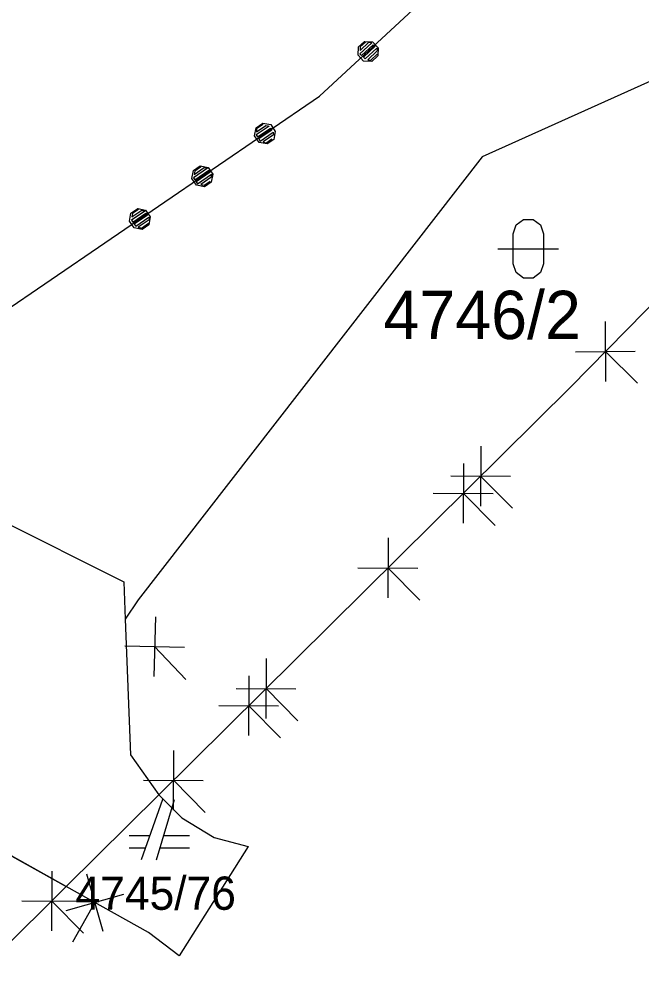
# Model space of a CAD drawing. Extents: x -266179 to -264727, y -1243225 to -1241702.
# Drawn here: x -265749.17 to -265728.53, y -1241952.44 to -1241920.85 of the extents above; entities that cross this region are included whole.
import ezdxf

# ---------------------------------------------------------------- set-up
doc = ezdxf.new("R2010")
doc.units = 0
for name, color, linetype in [('Vrstva 1', 7, 'Continuous'), ('Vrstva 19', 7, 'Continuous'), ('Vrstva 21', 7, 'Continuous')]:
    doc.layers.add(name, color=color, linetype=linetype)

msp = doc.modelspace()

# ---------------------------------------------------------------- linework, layer by layer
at = {"layer": 'Vrstva 1'}
for p, q in [((-265739.22, -1241923.41), (-265729.78, -1241914.67)), ((-265715.41, -1241917.13), (-265733.82, -1241925.42)), ((-265719.23, -1241921.16), (-265730.9, -1241933.04)), ((-265755.57, -1241934.56), (-265739.22, -1241923.41)), ((-265733.82, -1241925.42), (-265745.23, -1241940.09)), ((-265730.9, -1241933.04), (-265744.54, -1241946.54)), ((-265755.57, -1241934.56), (-265745.7, -1241939.49)), ((-265745.7, -1241939.49), (-265745.65, -1241940.73)), ((-265745.23, -1241940.09), (-265745.65, -1241940.73)), ((-265745.65, -1241940.73), (-265745.48, -1241945.22)), ((-265745.48, -1241945.22), (-265744.54, -1241946.54)), ((-265744.54, -1241946.54), (-265747.61, -1241949.58)), ((-265744.42, -1241946.7), (-265745.12, -1241948.7)), ((-265744.62, -1241948.7), (-265744.02, -1241946.7)), ((-265744.54, -1241946.54), (-265743.78, -1241947.3)), ((-265743.78, -1241947.3), (-265742.71, -1241947.96)), ((-265747.61, -1241949.58), (-265751.03, -1241947.67)), ((-265744.84, -1241947.9), (-265745.52, -1241947.9)), ((-265743.52, -1241947.9), (-265744.38, -1241947.9)), ((-265742.71, -1241947.96), (-265741.58, -1241948.25)), ((-265745.52, -1241948.3), (-265744.98, -1241948.3)), ((-265744.5, -1241948.3), (-265743.52, -1241948.3)), ((-265741.58, -1241948.25), (-265743.87, -1241951.87)), ((-265747.61, -1241949.58), (-265756.26, -1241958.14)), ((-265744.88, -1241951.1), (-265747.61, -1241949.58)), ((-265743.87, -1241951.87), (-265744.88, -1241951.1))]:
    msp.add_line(p, q, dxfattribs=at)
msp.add_lwpolyline([(-265732.8, -1241927.96), (-265732.7, -1241927.67), (-265732.45, -1241927.49), (-265732.14, -1241927.49), (-265731.89, -1241927.67), (-265731.79, -1241927.96), (-265731.79, -1241928.96), (-265731.89, -1241929.25), (-265732.14, -1241929.43), (-265732.45, -1241929.43), (-265732.7, -1241929.25), (-265732.8, -1241928.96)], close=True, dxfattribs=at)
msp.add_lwpolyline([(-265733.3, -1241928.46), (-265732.03, -1241928.46), (-265731.3, -1241928.46)], dxfattribs=at)
at = {"layer": 'Vrstva 19'}
for p, q in [((-265739.22, -1241923.41), (-265729.78, -1241914.67)), ((-265755.57, -1241934.56), (-265739.22, -1241923.41))]:
    msp.add_line(p, q, dxfattribs=at)
for points in [[(-265737.728, -1241921.592), (-265737.459, -1241921.603), (-265737.276, -1241921.801), (-265737.286, -1241922.069), (-265737.484, -1241922.253), (-265737.753, -1241922.242), (-265737.936, -1241922.044), (-265737.926, -1241921.776), (-265737.728, -1241921.592), (-265737.693, -1241921.615), (-265737.869, -1241921.778), (-265737.873, -1241921.891), (-265737.58, -1241921.619), (-265737.482, -1241921.637), (-265737.878, -1241922.004), (-265737.823, -1241922.063), (-265737.435, -1241921.703), (-265737.373, -1241921.755), (-265737.762, -1241922.115), (-265737.707, -1241922.173), (-265737.319, -1241921.813), (-265737.301, -1241921.906), (-265737.616, -1241922.198), (-265737.511, -1241922.209), (-265737.305, -1241922.019)], [(-265741.095, -1241924.3), (-265740.831, -1241924.349), (-265740.679, -1241924.572), (-265740.728, -1241924.836), (-265740.951, -1241924.989), (-265741.215, -1241924.939), (-265741.368, -1241924.716), (-265741.318, -1241924.452), (-265741.095, -1241924.3), (-265741.105, -1241924.355), (-265741.304, -1241924.491), (-265741.308, -1241924.59), (-265740.994, -1241924.376), (-265740.883, -1241924.397), (-265741.312, -1241924.69), (-265741.267, -1241924.756), (-265740.838, -1241924.463), (-265740.793, -1241924.529), (-265741.222, -1241924.822), (-265741.185, -1241924.894), (-265740.756, -1241924.601), (-265740.744, -1241924.69), (-265741.082, -1241924.921), (-265740.996, -1241924.959), (-265740.798, -1241924.823)], [(-265743.168, -1241925.715), (-265742.904, -1241925.765), (-265742.752, -1241925.988), (-265742.801, -1241926.252), (-265743.024, -1241926.404), (-265743.288, -1241926.354), (-265743.441, -1241926.131), (-265743.391, -1241925.867), (-265743.168, -1241925.715), (-265743.154, -1241925.754), (-265743.352, -1241925.889), (-265743.373, -1241926), (-265743.042, -1241925.774), (-265742.931, -1241925.795), (-265743.394, -1241926.111), (-265743.349, -1241926.177), (-265742.886, -1241925.862), (-265742.841, -1241925.928), (-265743.303, -1241926.243), (-265743.258, -1241926.309), (-265742.796, -1241925.994), (-265742.817, -1241926.105), (-265743.147, -1241926.33), (-265743.036, -1241926.351), (-265742.838, -1241926.216)], [(-265745.241, -1241927.13), (-265744.977, -1241927.18), (-265744.825, -1241927.403), (-265744.874, -1241927.667), (-265745.097, -1241927.819), (-265745.361, -1241927.769), (-265745.514, -1241927.546), (-265745.464, -1241927.282), (-265745.241, -1241927.13), (-265745.21, -1241927.157), (-265745.408, -1241927.293), (-265745.429, -1241927.404), (-265745.099, -1241927.178), (-265745.004, -1241927.211), (-265745.45, -1241927.515), (-265745.405, -1241927.581), (-265744.967, -1241927.282), (-265744.914, -1241927.343), (-265745.352, -1241927.642), (-265745.307, -1241927.708), (-265744.869, -1241927.409), (-265744.865, -1241927.503), (-265745.22, -1241927.746), (-265745.117, -1241927.772), (-265744.886, -1241927.614)]]:
    msp.add_lwpolyline(points, dxfattribs=at)
at = {"layer": 'Vrstva 21'}
for p, q in [((-265739.22, -1241923.41), (-265729.78, -1241914.67)), ((-265719.23, -1241921.16), (-265730.9, -1241933.04)), ((-265730.9, -1241933.04), (-265719.23, -1241921.16)), ((-265755.57, -1241934.56), (-265739.22, -1241923.41)), ((-265729.751, -1241930.87), (-265729.734, -1241932.85)), ((-265730.733, -1241931.868), (-265728.753, -1241931.851)), ((-265729.743, -1241931.86), (-265728.673, -1241932.911)), ((-265730.9, -1241933.04), (-265744.54, -1241946.54)), ((-265744.54, -1241946.54), (-265730.9, -1241933.04)), ((-265733.873, -1241934.999), (-265733.883, -1241936.979)), ((-265734.448, -1241935.568), (-265734.458, -1241937.548)), ((-265734.868, -1241935.984), (-265732.888, -1241935.994)), ((-265733.878, -1241935.989), (-265732.823, -1241937.055)), ((-265735.443, -1241936.553), (-265733.463, -1241936.563)), ((-265734.453, -1241936.558), (-265733.398, -1241937.624)), ((-265736.944, -1241938.037), (-265736.955, -1241940.017)), ((-265737.94, -1241939.022), (-265735.96, -1241939.033)), ((-265736.95, -1241939.027), (-265735.895, -1241940.094)), ((-265744.655, -1241940.643), (-265744.706, -1241942.622)), ((-265745.67, -1241941.608), (-265743.691, -1241941.658)), ((-265744.681, -1241941.633), (-265743.647, -1241942.72)), ((-265740.982, -1241942.032), (-265740.992, -1241944.012)), ((-265741.557, -1241942.601), (-265741.567, -1241944.581)), ((-265741.977, -1241943.017), (-265739.997, -1241943.027)), ((-265740.987, -1241943.022), (-265739.932, -1241944.088)), ((-265742.552, -1241943.586), (-265740.572, -1241943.596)), ((-265741.562, -1241943.591), (-265740.507, -1241944.657)), ((-265744.054, -1241945.07), (-265744.064, -1241947.05)), ((-265745.049, -1241946.055), (-265743.069, -1241946.065)), ((-265744.059, -1241946.06), (-265743.004, -1241947.127)), ((-265744.54, -1241946.54), (-265747.61, -1241949.58)), ((-265747.61, -1241949.58), (-265744.54, -1241946.54)), ((-265747.61, -1241949.58), (-265751.03, -1241947.67)), ((-265751.03, -1241947.67), (-265747.61, -1241949.58)), ((-265748.086, -1241949.07), (-265748.096, -1241951.05)), ((-265746.935, -1241949.156), (-265746.395, -1241951.061)), ((-265745.713, -1241949.839), (-265747.617, -1241950.379)), ((-265749.081, -1241950.055), (-265747.101, -1241950.065)), ((-265748.091, -1241950.06), (-265747.036, -1241951.126)), ((-265746.665, -1241950.109), (-265747.396, -1241951.418))]:
    msp.add_line(p, q, dxfattribs=at)

# ---------------------------------------------------------------- texts
at = {"layer": 'Vrstva 1'}
for s, height, p in [('4746/2', 1.6, (-265737.097, -1241931.45)), ('4745/76', 1.1, (-265747.302, -1241950.35))]:
    msp.add_text(s, height=height, dxfattribs=at).set_placement(p)

doc.saveas('drawing.dxf')
